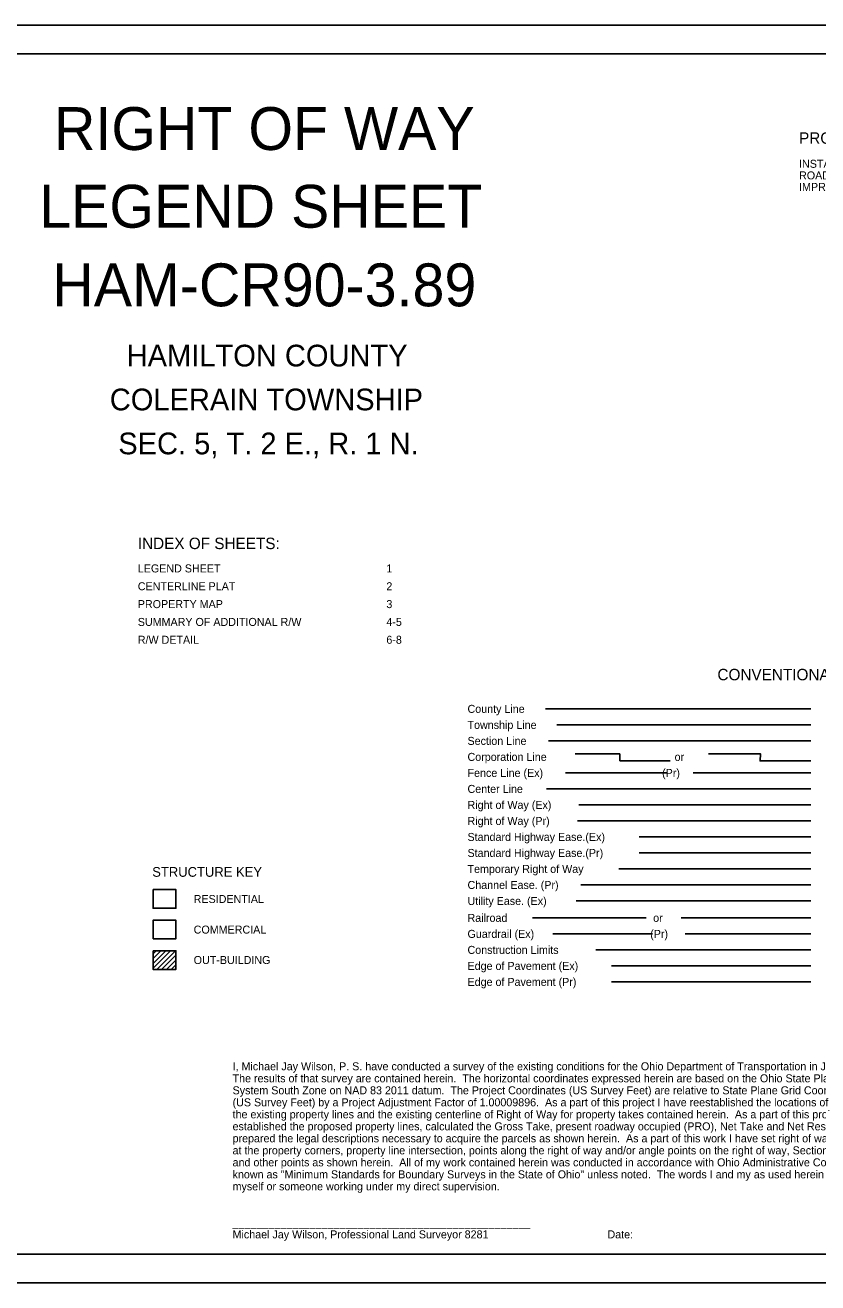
# Model space of a CAD drawing. Extents: x 0 to 34, y 0 to 22.
# Drawn here: x 11.72 to 25.58, y 0 to 22 of the extents above; entities that cross this region are included whole.
import ezdxf

# ---------------------------------------------------------------- set-up
doc = ezdxf.new("R2010")
doc.units = 0
for name, color, linetype in [('SC_Shading1', 7, 'Continuous'), ('SH_Border', 7, 'Continuous'), ('SH_Cut_Line', 7, 'Continuous'), ('SH_Data', 7, 'Continuous'), ('SH_Text', 7, 'Continuous')]:
    doc.layers.add(name, color=color, linetype=linetype)

msp = doc.modelspace()

# ---------------------------------------------------------------- linework, layer by layer
at = {"layer": 'SC_Shading1'}
msp.add_lwpolyline([(13.96, 6.019), (14.357, 6.019), (14.357, 6.344), (13.96, 6.344)], close=True, dxfattribs=at)
at = {"layer": 'SH_Border'}
msp.add_lwpolyline([(1.5, 21.5), (33.5, 21.5), (33.5, 0.5), (1.5, 0.5)], close=True, dxfattribs=at)
at = {"layer": 'SH_Cut_Line'}
msp.add_lwpolyline([(0, 0), (34, 0), (34, 22), (0, 22)], close=True, dxfattribs=at)
at = {"layer": 'SH_Text'}
for p, q in [((20.818, 10.04), (25.457, 10.04)), ((21.016, 9.76), (25.457, 9.76)), ((20.873, 9.48), (25.457, 9.48)), ((21.337, 9.256), (22.12, 9.256)), ((22.12, 9.256), (22.12, 9.13)), ((22.12, 9.13), (23.001, 9.13)), ((21.17, 8.92), (22.943, 8.92)), ((23.4, 8.92), (25.457, 8.92)), ((20.839, 8.64), (25.457, 8.64)), ((21.406, 8.36), (25.457, 8.36)), ((21.378, 8.08), (25.457, 8.08)), ((22.457, 7.8), (25.457, 7.8)), ((22.457, 7.52), (25.457, 7.52)), ((22.102, 7.24), (25.457, 7.24)), ((21.44, 6.96), (25.457, 6.96)), ((21.356, 6.68), (25.457, 6.68)), ((20.595, 6.384), (22.581, 6.384)), ((23.19, 6.384), (25.457, 6.384)), ((20.949, 6.104), (22.692, 6.104)), ((23.262, 6.104), (25.457, 6.104)), ((13.96, 5.808), (13.961, 5.809)), ((13.96, 5.758), (14.011, 5.809)), ((13.96, 5.673), (14.096, 5.809)), ((13.96, 5.588), (14.18, 5.809)), ((13.96, 5.504), (14.265, 5.809)), ((14.024, 5.483), (14.35, 5.809)), ((14.109, 5.483), (14.357, 5.731)), ((21.701, 5.824), (25.457, 5.824)), ((14.193, 5.483), (14.357, 5.647)), ((14.278, 5.483), (14.357, 5.562)), ((21.973, 5.544), (25.457, 5.544)), ((13.96, 5.488), (13.964, 5.483)), ((21.973, 5.264), (25.457, 5.264))]:
    msp.add_line(p, q, dxfattribs=at)
msp.add_lwpolyline([(23.673, 9.256), (24.577, 9.256), (24.571, 9.13), (25.457, 9.13)], dxfattribs=at)
for points in [[(13.96, 6.88), (14.357, 6.88), (14.357, 6.554), (13.96, 6.554)], [(13.96, 5.809), (14.357, 5.809), (14.357, 5.483), (13.96, 5.483)]]:
    msp.add_lwpolyline(points, close=True, dxfattribs=at)

# ---------------------------------------------------------------- texts
at = {"layer": 'SH_Data'}
for s, height, p in [('RIGHT OF WAY', 0.75, (12.227, 19.816)), ('PROJECT DESCRIPTION', 0.2, (25.254, 19.925)), ('INSTALLING A NEW SIDEWALK ALONG THE WEST SIDE OF PIPPIN ', 0.14, (25.254, 19.505)), ('ROAD BETWEEN STRUBLE ROAD AND STOUT ROAD AND ', 0.14, (25.254, 19.302)), ('LEGEND SHEET', 0.75, (11.968, 18.457)), ('IMPROVING THE CROSSINGS AT THE INTERSECTIONS.', 0.14, (25.254, 19.1)), ('HAM-CR90-3.89', 0.75, (12.198, 17.082)), ('HAMILTON COUNTY', 0.38, (13.497, 16.03)), ('COLERAIN TOWNSHIP', 0.38, (13.202, 15.262)), ('SEC. 5, T. 2 E., R. 1 N.', 0.38, (13.35, 14.493)), ('INDEX OF SHEETS:', 0.2, (13.692, 12.835)), ('LEGEND SHEET', 0.14, (13.692, 12.427)), ('1', 0.14, (18.038, 12.427)), ('CENTERLINE PLAT', 0.14, (13.692, 12.115)), ('2', 0.14, (18.038, 12.115)), ('PROPERTY MAP', 0.14, (13.692, 11.803)), ('3', 0.14, (18.038, 11.803)), ('SUMMARY OF ADDITIONAL R/W', 0.14, (13.692, 11.491)), ('4-5', 0.14, (18.038, 11.491)), ('R/W DETAIL', 0.14, (13.692, 11.179)), ('6-8', 0.14, (18.038, 11.179))]:
    msp.add_text(s, height=height, dxfattribs=at).set_placement(p)
at = {"layer": 'SH_Text'}
for s, height, p in [('CONVENTIONAL SYMBOLS', 0.2, (23.827, 10.54)), ('County Line', 0.14, (19.457, 9.97)), ('Township Line', 0.14, (19.457, 9.69)), ('Section Line', 0.14, (19.457, 9.41)), ('Corporation Line                                           or', 0.14, (19.457, 9.13)), ('Fence Line (Ex)                                        (Pr)', 0.14, (19.457, 8.85)), ('Center Line', 0.14, (19.457, 8.57)), ('Right of Way (Ex)', 0.14, (19.457, 8.29)), ('Right of Way (Pr)', 0.14, (19.457, 8.01)), ('Standard Highway Ease.(Ex)', 0.14, (19.457, 7.73)), ('Standard Highway Ease.(Pr)', 0.14, (19.457, 7.45)), ('STRUCTURE KEY', 0.17, (13.944, 7.103)), ('Temporary Right of Way', 0.14, (19.457, 7.17)), ('Channel Ease. (Pr)', 0.14, (19.457, 6.89)), ('RESIDENTIAL', 0.14, (14.669, 6.644)), ('Utility Ease. (Ex)', 0.14, (19.457, 6.61)), ('Railroad                                                 or', 0.14, (19.457, 6.314)), ('COMMERCIAL', 0.14, (14.669, 6.109)), ('Guardrail (Ex)                                       (Pr)', 0.14, (19.457, 6.034)), ('Construction Limits', 0.14, (19.457, 5.754)), ('OUT-BUILDING', 0.14, (14.669, 5.577)), ('Edge of Pavement (Ex)', 0.14, (19.457, 5.474)), ('Edge of Pavement (Pr)', 0.14, (19.457, 5.194)), ('I, Michael Jay Wilson, P. S. have conducted a survey of the existing conditions for the Ohio Department of Transportation in June, 2021.', 0.14, (15.349, 3.718)), ('The results of that survey are contained herein.  The horizontal coordinates expressed herein are based on the Ohio State Plane Coordinates', 0.14, (15.349, 3.508)), ('System South Zone on NAD 83 2011 datum.  The Project Coordinates (US Survey Feet) are relative to State Plane Grid Coordinates', 0.14, (15.349, 3.298)), ('(US Survey Feet) by a Project Adjustment Factor of 1.00009896.  As a part of this project I have reestablished the locations of', 0.14, (15.349, 3.088)), ('the existing property lines and the existing centerline of Right of Way for property takes contained herein.  As a part of this project I have', 0.14, (15.349, 2.878)), ('established the proposed property lines, calculated the Gross Take, present roadway occupied (PRO), Net Take and Net Residue; as well as', 0.14, (15.349, 2.668)), ('prepared the legal descriptions necessary to acquire the parcels as shown herein.  As a part of this work I have set right of way monuments', 0.14, (15.349, 2.458)), ('at the property corners, property line intersection, points along the right of way and/or angle points on the right of way, Section Corners', 0.14, (15.349, 2.248)), ('and other points as shown herein.  All of my work contained herein was conducted in accordance with Ohio Administrative Code 4733-37 commonly', 0.14, (15.349, 2.038)), ('known as "Minimum Standards for Boundary Surveys in the State of Ohio" unless noted.  The words I and my as used herein are to mean either', 0.14, (15.349, 1.828)), ('myself or someone working under my direct supervision.', 0.14, (15.349, 1.618)), ('__________________________________________________                                        ', 0.14, (15.349, 0.988)), ('Michael Jay Wilson, Professional Land Surveyor 8281                                        Date:                  ', 0.14, (15.349, 0.778))]:
    msp.add_text(s, height=height, dxfattribs=at).set_placement(p)

doc.saveas('drawing.dxf')
